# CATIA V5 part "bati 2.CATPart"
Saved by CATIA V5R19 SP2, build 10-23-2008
Part number: bati 2
Bounding box of the stored display mesh (mm): x -120 to -115, y 2.5 to 17.5, z -7.49 to 7.49
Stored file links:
  C:\Users\Thinkmotion2\Desktop\Pack 1\IAO_2010_1396_fvigouroux\vigouroux\vigouroux\bati 2.CATPart
  C:\Users\Thinkmotion2\Desktop\Pack 1\IAO_2010_1396_fvigouroux\vigouroux\vigouroux\mecanisme IAO.CATProduct
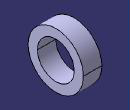
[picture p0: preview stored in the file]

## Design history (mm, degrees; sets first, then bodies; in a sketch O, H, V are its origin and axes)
External parameters (linked from other documents)
  `External.diametre arbre sortie` = 5 mm
Set1
  Plane1: linked copy from another document
  Point1: linked copy from another document
Body1 (main body)
  Sketch1 on Plane1, origin (-120, 0, 0), H (0, 1, 0), V (0, 0, 1)
    circle A1 centre (10, 0) radius 5
    point P1 (10, 0)
    reference projected point E1 (10, 0) from Point1
    circle A2 centre (10, 0) radius 7.5
    distance E1 P1 = 0
    radius A2 = 7.5
    radius A1 = 5 {= `External.diametre arbre sortie`}
    coincidence: P1 H
  Pad1: profile Sketch1, direction (1, 0, 0), length 5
